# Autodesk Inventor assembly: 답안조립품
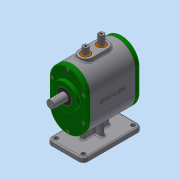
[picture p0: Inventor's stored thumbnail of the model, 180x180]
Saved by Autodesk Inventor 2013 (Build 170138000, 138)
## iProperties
Created: 2018-10
Part Number: 답안조립품
Document SubType Name: Assembly
Designer: Administrator
Author: Administrator
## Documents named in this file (15)
- C:\Users\Administrator\Desktop\381007V1026\답안조립품.iam
- C:\Users\Administrator\Desktop\381007V1026\본체.ipt
- C:\Users\Administrator\Desktop\381007V1026\뒤커버.ipt
- C:\Users\Administrator\Desktop\381007V1026\메인축.ipt
- C:\Users\Administrator\Desktop\381007V1026\베어링 608.ipt
- C:\Users\Administrator\Desktop\381007V1026\베어링 6003.ipt
- C:\Users\Administrator\Desktop\381007V1026\볼트 M4.ipt
- C:\Users\Administrator\Desktop\381007V1026\부시.ipt
- C:\Users\Administrator\Desktop\381007V1026\서브축.ipt
- C:\Users\Administrator\Desktop\381007V1026\슬라이더.ipt
- C:\Users\Administrator\Desktop\381007V1026\앞커버.ipt
- C:\Users\Administrator\Desktop\381007V1026\오일실 8 22 7.ipt
- C:\Users\Administrator\Desktop\381007V1026\오일실 17 32 8.ipt
- C:\Users\Administrator\Desktop\381007V1026\가변스프링1.ipt
- C:\Users\Administrator\Desktop\381007V1026\가변스프링2.ipt
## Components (2 placed, 2 different names)
1. 가변스프링1:1
2. 가변스프링2:1
